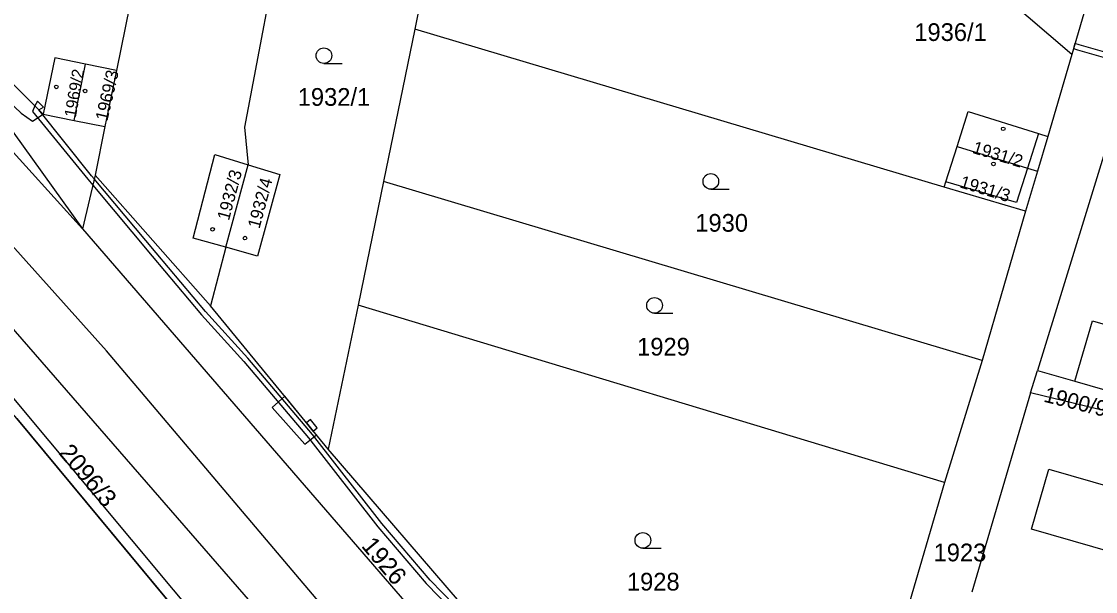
# Model space of a CAD drawing. Extents: x -756746 to -753363, y -1166406 to -1161727.
# Drawn here: x -755238.8 to -755135.8, y -1164967.1 to -1164912.5 of the extents above; entities that cross this region are included whole.
import ezdxf

# ---------------------------------------------------------------- set-up
doc = ezdxf.new("R2010")
doc.units = 0
for name, color, linetype in [('Hranice parcel', 7, 'Continuous'), ('Parcelní čísla', 7, 'Continuous'), ('Poz předměty', 7, 'Continuous'), ('Vnitřní kresba', 7, 'Continuous'), ('Věcná břemena k části', 7, 'Continuous'), ('Značky budov', 7, 'Continuous'), ('Značky kultur', 7, 'Continuous')]:
    doc.layers.add(name, color=color, linetype=linetype)

msp = doc.modelspace()

# ---------------------------------------------------------------- linework, layer by layer
at = {"layer": 'Hranice parcel'}
for p, q in [((-755263.55, -1164898.59), (-755232.98, -1164932.34)), ((-755198.5, -1164900.22), (-755201.07, -1164913.21)), ((-755138.07, -1164915.62), (-755148.4, -1164906.75)), ((-755135.91, -1164908.29), (-755138.07, -1164915.62)), ((-755130.08, -1164909.27), (-755141.36, -1164945.93)), ((-755201.07, -1164913.21), (-755204.09, -1164927.8)), ((-755150.3, -1164928.35), (-755201.07, -1164913.21)), ((-755138.07, -1164915.62), (-755140.36, -1164923.49)), ((-755233.76, -1164921.95), (-755232.67, -1164916.55)), ((-755229.72, -1164917.15), (-755232.67, -1164916.55)), ((-755229.72, -1164917.15), (-755230.82, -1164922.54)), ((-755239.99, -1164918.1), (-755236.73, -1164921.35)), ((-755236.73, -1164921.35), (-755233.76, -1164921.95)), ((-755233.76, -1164921.95), (-755230.82, -1164922.54)), ((-755230.82, -1164922.54), (-755231.76, -1164927.2)), ((-755140.36, -1164923.49), (-755141.35, -1164926.82)), ((-755219.22, -1164934.12), (-755217.08, -1164926.2)), ((-755141.35, -1164926.82), (-755142.51, -1164930.67)), ((-755231.76, -1164927.2), (-755232.98, -1164932.34)), ((-755220.69, -1164939.75), (-755231.76, -1164927.2)), ((-755204.09, -1164927.8), (-755206.52, -1164939.68)), ((-755146.65, -1164944.98), (-755204.09, -1164927.8)), ((-755142.51, -1164930.67), (-755150.3, -1164928.35)), ((-755142.51, -1164930.67), (-755146.65, -1164944.98)), ((-755232.98, -1164932.34), (-755197.4, -1164973.47)), ((-755219.22, -1164934.12), (-755220.69, -1164939.75)), ((-755209.4, -1164953.49), (-755220.69, -1164939.75)), ((-755206.52, -1164939.68), (-755209.4, -1164953.49)), ((-755150.26, -1164956.7), (-755206.52, -1164939.68)), ((-755146.65, -1164944.98), (-755150.26, -1164956.7)), ((-755142.02, -1164948.09), (-755141.36, -1164945.93)), ((-755141.36, -1164945.93), (-755137.78, -1164946.96)), ((-755137.78, -1164946.96), (-755088.56, -1164961.12)), ((-755142.02, -1164948.09), (-755147.65, -1164967.22)), ((-755088.56, -1164961.12), (-755142.02, -1164948.09)), ((-755150.26, -1164956.7), (-755159.39, -1164987.78))]:
    msp.add_line(p, q, dxfattribs=at)
for points in [[(-755174.51, -1165028.57), (-755173.62, -1165021.77), (-755210, -1164975.99), (-755240.66, -1164940.74), (-755264.36, -1164914.76), (-755305.85, -1164872.21)], [(-755222.16, -1164879.9), (-755224.21, -1164890.04), (-755229.72, -1164917.15)], [(-755174.51, -1165028.57), (-755239.27, -1164950.56), (-755255.53, -1164931.93), (-755293.61, -1164892.37), (-755304.73, -1164881.59)], [(-755262.92, -1164894.69), (-755248.27, -1164911.07), (-755232.98, -1164932.34)], [(-755213.61, -1164902.48), (-755217.42, -1164922.61), (-755217.08, -1164926.2)], [(-755232.67, -1164916.55), (-755235.62, -1164915.96), (-755236.73, -1164921.35)], [(-755149.07, -1164924.47), (-755148.01, -1164921.09), (-755141.26, -1164923.21), (-755140.36, -1164923.49)], [(-755150.3, -1164928.35), (-755150.13, -1164927.84), (-755149.07, -1164924.47)], [(-755149.07, -1164924.47), (-755142.32, -1164926.53), (-755141.35, -1164926.82)], [(-755219.22, -1164934.12), (-755222.35, -1164933.24), (-755220.26, -1164925.22), (-755217.08, -1164926.2)], [(-755217.08, -1164926.2), (-755214.05, -1164927.14), (-755216.18, -1164934.96), (-755219.22, -1164934.12)], [(-755137.78, -1164946.96), (-755136.08, -1164941.17), (-755054.29, -1164964.71)], [(-755159.39, -1164987.78), (-755195.43, -1164969.72), (-755209.4, -1164953.49)], [(-755140.25, -1164955.42), (-755056.4, -1164979.54), (-755058.13, -1164985.32), (-755141.94, -1164961.18), (-755140.25, -1164955.42)]]:
    msp.add_lwpolyline(points, dxfattribs=at)
at = {"layer": 'Poz předměty'}
for p, q in [((-755230.66, -1164944.05), (-755259.59, -1164911.85)), ((-755204.91, -1164974.48), (-755230.66, -1164944.05))]:
    msp.add_line(p, q, dxfattribs=at)
at = {"layer": 'Vnitřní kresba'}
for p, q in [((-755141.26, -1164923.21), (-755142.32, -1164926.53)), ((-755142.32, -1164926.53), (-755143.37, -1164929.84)), ((-755143.37, -1164929.84), (-755150.13, -1164927.84))]:
    msp.add_line(p, q, dxfattribs=at)
at = {"layer": 'Věcná břemena k části'}
for points in [[(-755061.78, -1164937.31), (-755061.27, -1164937.33), (-755061.22, -1164937.12), (-755062.03, -1164936.52), (-755074.09, -1164932.97), (-755091.75, -1164927.79), (-755107.58, -1164923.08), (-755119.23, -1164919.5), (-755130.35, -1164916.09), (-755132.21, -1164916.18), (-755137.36, -1164914.69), (-755137.76, -1164914.57), (-755137.9, -1164915.05), (-755137.5, -1164915.17), (-755132.35, -1164916.65), (-755130.41, -1164916.59), (-755119.65, -1164919.89), (-755119.98, -1164920.6), (-755119.49, -1164920.74), (-755119.16, -1164920.04), (-755107.72, -1164923.56), (-755091.89, -1164928.27), (-755074.23, -1164933.45), (-755062.25, -1164936.98)], [(-755237.75, -1164922.03), (-755236.73, -1164921.35), (-755237.15, -1164920.94), (-755237.54, -1164920.54), (-755239.99, -1164918.1), (-755240.85, -1164917.2), (-755240.4, -1164916.78), (-755241.09, -1164916.05), (-755241.54, -1164916.48), (-755241.89, -1164916.11), (-755242.52, -1164917.25), (-755241.44, -1164918.39), (-755240.11, -1164920.08), (-755238.86, -1164921.26)], [(-755237.54, -1164920.54), (-755237.15, -1164920.94), (-755236.71, -1164920.67), (-755237.27, -1164920.1)], [(-755236.71, -1164920.67), (-755237.27, -1164920.1), (-755237.54, -1164920.54), (-755237.15, -1164920.94)], [(-755211.63, -1164953), (-755210.52, -1164952.13), (-755210.83, -1164951.75), (-755211.47, -1164950.97), (-755213.57, -1164948.42), (-755214.77, -1164949.49)], [(-755211.47, -1164950.97), (-755210.83, -1164951.75), (-755210.45, -1164951.43), (-755211.08, -1164950.66)]]:
    msp.add_lwpolyline(points, close=True, dxfattribs=at)
for points in [[(-755197.26, -1164968.49), (-755199.61, -1164966.05), (-755204.25, -1164960.61), (-755210.9, -1164952.07), (-755217.11, -1164944.76), (-755221.16, -1164940.28), (-755225.9, -1164934.65), (-755231.85, -1164927.56), (-755232.09, -1164927.27), (-755237.15, -1164920.94), (-755237.54, -1164920.54), (-755237.76, -1164921.09), (-755232.47, -1164927.59), (-755231.99, -1164928.16), (-755226.28, -1164934.97), (-755221.54, -1164940.6), (-755217.49, -1164945.08), (-755211.28, -1164952.39), (-755204.63, -1164960.93), (-755199.99, -1164966.39), (-755197.6, -1164968.85)], [(-755239.53, -1165044.65), (-755238.3, -1165039.63), (-755237.89, -1165039.52), (-755224.72, -1165041.39), (-755221.89, -1165040.94), (-755219.47, -1165040.02), (-755217.33, -1165038.61), (-755215.87, -1165035.54), (-755204.97, -1165029.98), (-755197.27, -1165024.48), (-755185.72, -1165015.07), (-755185.21, -1165014.43), (-755185.42, -1165013.47), (-755220.2, -1164971.82), (-755244.26, -1164943.04)], [(-755239.27, -1164950.56), (-755208.04, -1164988.18), (-755207.36, -1164988.47), (-755186.34, -1165013.91), (-755186.37, -1165014.29), (-755197.9, -1165023.7), (-755205.49, -1165029.12), (-755214, -1165033.67), (-755216.63, -1165034.8), (-755218.11, -1165037.93), (-755219.93, -1165039.12), (-755222.15, -1165039.96), (-755224.72, -1165040.37), (-755237.96, -1165038.5), (-755239.13, -1165038.83)]]:
    msp.add_lwpolyline(points, dxfattribs=at)
at = {"layer": 'Značky budov'}
for centre in [(-755235.48, -1164918.74), (-755232.72, -1164919.13), (-755144.64, -1164922.76), (-755145.58, -1164926.12), (-755220.49, -1164932.4), (-755217.38, -1164933.24)]:
    msp.add_circle(centre, 0.175, dxfattribs=at)
at = {"layer": 'Značky kultur'}
for p, q in [((-755209.81, -1164916.49), (-755208.06, -1164916.49)), ((-755172.69, -1164928.55), (-755170.94, -1164928.55)), ((-755178.09, -1164940.45), (-755176.34, -1164940.45)), ((-755179.21, -1164962.99), (-755177.46, -1164962.99))]:
    msp.add_line(p, q, dxfattribs=at)
for centre in [(-755209.81, -1164915.74), (-755172.69, -1164927.8), (-755178.09, -1164939.7), (-755179.21, -1164962.24)]:
    msp.add_circle(centre, 0.75, dxfattribs=at)

# ---------------------------------------------------------------- texts
at = {"layer": 'Parcelní čísla'}
for s, p in [('1936/1', (-755153.17, -1164914.33)), ('1932/1', (-755212.32, -1164920.55)), ('1930', (-755174.18, -1164932.63)), ('1929', (-755179.76, -1164944.51)), ('1923', (-755151.32, -1164964.25)), ('1928', (-755180.74, -1164967.05))]:
    msp.add_text(s, height=1.7, dxfattribs=at).set_placement(p)
for s, height, rotation, p in [('1969/2', 1.139, 80, (-755233.61, -1164921.73)), ('1969/3', 1.2, 77, (-755230.58, -1164922.06)), ('1931/2', 1.2, 343, (-755147.67, -1164925.06)), ('1932/3', 1.2, 75, (-755218.92, -1164931.62)), ('1932/4', 1.2, 75, (-755215.99, -1164932.4)), ('1931/3', 1.2, 343, (-755148.88, -1164928.36)), ('1900/97', 1.5, 346, (-755140.84, -1164948.92)), ('2096/3', 1.7, 310, (-755235.32, -1164953.88)), ('1926', 1.7, 310, (-755206.29, -1164962.8))]:
    msp.add_text(s, height=height, rotation=rotation, dxfattribs=at).set_placement(p)

doc.saveas('drawing.dxf')
